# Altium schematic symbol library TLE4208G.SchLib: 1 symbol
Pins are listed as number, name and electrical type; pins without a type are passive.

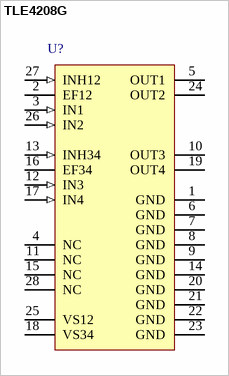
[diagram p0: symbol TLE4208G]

## TLE4208G
designator U?
1 A Quad-HBD (Quad-Half-Bridge Driver), -40 to 150 degC, PG-DSO-28-24, Reel, Green; Manufacturer: Infineon; PartNumber: TLE4208G; Green: TRUE; Group: Multi Half Bridges; IPeak: 4 x 1 A; Iq: 4 x 0.8 A; Iq (typ): 20 uA; Protect: short circuit
footprint INF-PG-DSO-28-24_N (SOP, 28-Leads, Body 17.9x7.5mm, Pitch 1.27mm, IPC Medium Density)
footprint INF-PG-DSO-28-24_L (SOP, 28-Leads, Body 17.9x7.5mm, Pitch 1.27mm, IPC High Density)
footprint INF-PG-DSO-28-24_M (SOP, 28-Leads, Body 17.9x7.5mm, Pitch 1.27mm, IPC Low Density)
pins: 1 GND (power) "Ground; negative reference potential for blocking capacitor", 2 EF12 (oc) "Error Flag output of half-bridges 1and 2; open collector; low = error", 3 IN1 (in) "Input channel of half-bridge 1; controls OUT1", 4 NC "Not connected", 5 OUT1 (power) "Power output of half-bridge 1; short circuit protected; with integrated clamp diodes", 6 GND (power) "Ground; negative reference potential for blocking capacitor", 7 GND (power) "Ground; negative reference potential for blocking capacitor", 8 GND (power) "Ground; negative reference potential for blocking capacitor", 9 GND (power) "Ground; negative reference potential for blocking capacitor", 10 OUT3 (power) "Power output of half-bridge 3; short-circuit protected; with integrated clamp diodes", 11 NC "Not connected", 12 IN3 (in) "Input channel of half-bridge 3; controls OUT3", 13 INH34 (in) "Inhibit input of half-bridges 3 and 4; low = half-bridges 3 and 4 in stand-by", 14 GND (power) "Ground; negative reference potential for blocking capacitor", 15 NC "Not connected", 16 EF34 (oc) "Error Flag output of half-bridges 3 and 4; open collector; low = error", 17 IN4 (in) "Input channel of half-bridge 4; controls OUT4", 18 VS34 (power) "Power supply voltage of half-bridges 3 and 4; positive reference potential for blocking capacitor", 19 OUT4 (power) "Power output of half-bridge 4; short circuit protected; with integrated clamp diodes", 20 GND (power) "Ground; negative reference potential for blocking capacitor", 21 GND (power) "Ground; negative reference potential for blocking capacitor", 22 GND (power) "Ground; negative reference potential for blocking capacitor", 23 GND (power) "Ground; negative reference potential for blocking capacitor", 24 OUT2 (power) "Power-output of half-bridge 2; short circuit protected; with integrated clamp diodes", 25 VS12 (power) "Power supply voltage of half-bridges 1 and 2; positive reference potential for blocking capacitor", 26 IN2 (in) "Input channel of half-bridge 2; controls OUT2", 27 INH12 (in) "Inhibit input of half-bridges 1and 2; low = half-bridges 1 and 2 in stand-by", 28 NC "Not connected"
